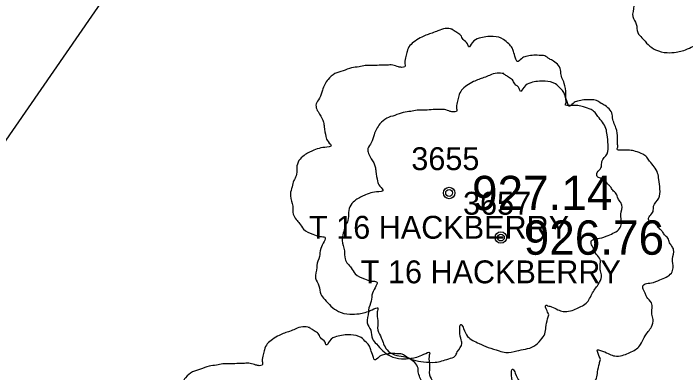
# Model space of a CAD drawing. Extents: x 1575382 to 1578175, y 1099175 to 1101955.
# Drawn here: x 1577367.12 to 1577396.51, y 1100879.44 to 1100895.14 of the extents above; entities that cross this region are included whole.
import ezdxf

# ---------------------------------------------------------------- set-up
doc = ezdxf.new("R2010")
doc.units = 0
for name, color, linetype in [('RD_EX_Conc', 7, 'Continuous'), ('RD_EX_TX_VEG_ELEV', 7, 'Continuous'), ('RD_EX_VEG', 7, 'Continuous'), ('RD_EX_VEG_txCode', 7, 'Continuous'), ('RD_SMD_Locator', 7, 'Continuous')]:
    doc.layers.add(name, color=color, linetype=linetype)

msp = doc.modelspace()

# ---------------------------------------------------------------- linework, layer by layer
at = {"layer": 'RD_EX_Conc'}
msp.add_lwpolyline([(1577353.203, 1100869.936), (1577378.592, 1100906.687), (1577381.828, 1100910.062), (1577386.394, 1100913.088)], dxfattribs=at)
at = {"layer": 'RD_EX_VEG'}
for centre, radius in [((1577386.17, 1100887.293), 0.25), ((1577386.157, 1100887.274), 0.0001), ((1577388.432, 1100885.344), 0.25), ((1577388.419, 1100885.325), 0.0001)]:
    msp.add_circle(centre, radius, dxfattribs=at)
for points in [[(1577400.17, 1100905.899), (1577399.87, 1100905.924), (1577399.545, 1100905.824), (1577399.295, 1100905.724), (1577399.07, 1100905.649), (1577398.845, 1100905.549), (1577398.545, 1100905.374), (1577398.321, 1100905.174), (1577398.196, 1100904.924), (1577398.146, 1100904.699), (1577398.096, 1100904.424), (1577398.096, 1100904.249), (1577397.971, 1100904.224), (1577397.821, 1100904.249), (1577397.571, 1100904.324), (1577397.321, 1100904.324), (1577397.071, 1100904.324), (1577396.721, 1100904.299), (1577396.371, 1100904.299), (1577396.097, 1100904.249), (1577395.772, 1100904.199), (1577395.397, 1100904.074), (1577395.047, 1100903.949), (1577394.747, 1100903.7), (1577394.497, 1100903.225), (1577394.372, 1100902.875), (1577394.222, 1100902.625), (1577394.372, 1100902.175), (1577394.547, 1100901.825), (1577394.572, 1100901.625), (1577394.647, 1100901.201), (1577394.747, 1100900.976), (1577394.872, 1100900.776), (1577394.797, 1100900.751), (1577394.422, 1100900.701), (1577394.122, 1100900.601), (1577393.698, 1100900.376), (1577393.473, 1100900.151), (1577393.373, 1100899.826), (1577393.348, 1100899.476), (1577393.248, 1100899.277), (1577393.173, 1100899.002), (1577393.148, 1100898.927), (1577393.098, 1100898.602), (1577393.198, 1100898.152), (1577393.223, 1100897.802), (1577393.348, 1100897.577), (1577393.498, 1100897.402), (1577393.673, 1100897.152), (1577394.072, 1100896.928), (1577394.397, 1100896.828), (1577394.597, 1100896.803), (1577394.422, 1100896.303), (1577394.372, 1100895.953), (1577394.247, 1100895.553), (1577394.247, 1100895.478), (1577394.197, 1100895.003), (1577394.347, 1100894.678), (1577394.422, 1100894.304), (1577394.597, 1100894.079), (1577394.872, 1100893.779), (1577395.197, 1100893.554), (1577395.697, 1100893.429), (1577396.097, 1100893.454), (1577396.671, 1100893.629), (1577396.921, 1100893.704), (1577396.896, 1100893.529), (1577396.921, 1100893.154), (1577396.921, 1100892.729), (1577397.071, 1100892.405), (1577397.171, 1100892.13), (1577397.321, 1100891.88), (1577397.646, 1100891.655), (1577398.046, 1100891.58), (1577398.47, 1100891.43), (1577398.92, 1100891.355), (1577399.42, 1100891.33), (1577400.02, 1100891.48), (1577400.295, 1100891.605), (1577400.395, 1100891.78), (1577400.595, 1100892.155), (1577400.545, 1100892.38), (1577400.57, 1100892.979), (1577400.669, 1100892.804), (1577400.844, 1100892.454), (1577401.344, 1100892.155), (1577401.744, 1100891.98), (1577402.219, 1100891.83), (1577402.519, 1100891.755), (1577402.993, 1100891.83), (1577403.368, 1100891.905), (1577403.743, 1100892.03), (1577404.043, 1100892.305), (1577404.218, 1100892.579), (1577404.268, 1100892.854), (1577404.343, 1100893.229), (1577404.393, 1100893.404)], [(1577386.302, 1100894.46), (1577386.002, 1100894.485), (1577385.677, 1100894.385), (1577385.427, 1100894.285), (1577385.202, 1100894.21), (1577384.978, 1100894.11), (1577384.678, 1100893.935), (1577384.453, 1100893.735), (1577384.328, 1100893.486), (1577384.278, 1100893.261), (1577384.228, 1100892.986), (1577384.228, 1100892.811), (1577384.103, 1100892.786), (1577383.953, 1100892.811), (1577383.703, 1100892.886), (1577383.453, 1100892.886), (1577383.203, 1100892.886), (1577382.853, 1100892.861), (1577382.504, 1100892.861), (1577382.229, 1100892.811), (1577381.904, 1100892.761), (1577381.529, 1100892.636), (1577381.179, 1100892.511), (1577380.879, 1100892.261), (1577380.629, 1100891.786), (1577380.504, 1100891.436), (1577380.355, 1100891.187), (1577380.504, 1100890.737), (1577380.679, 1100890.387), (1577380.704, 1100890.187), (1577380.779, 1100889.762), (1577380.879, 1100889.537), (1577381.004, 1100889.337), (1577380.929, 1100889.312), (1577380.554, 1100889.262), (1577380.255, 1100889.162), (1577379.83, 1100888.938), (1577379.605, 1100888.713), (1577379.505, 1100888.388), (1577379.48, 1100888.038), (1577379.38, 1100887.838), (1577379.305, 1100887.563), (1577379.28, 1100887.488), (1577379.23, 1100887.163), (1577379.33, 1100886.713), (1577379.355, 1100886.364), (1577379.48, 1100886.139), (1577379.63, 1100885.964), (1577379.805, 1100885.714), (1577380.205, 1100885.489), (1577380.529, 1100885.389), (1577380.729, 1100885.364), (1577380.554, 1100884.864), (1577380.504, 1100884.514), (1577380.38, 1100884.115), (1577380.38, 1100884.04), (1577380.33, 1100883.565), (1577380.479, 1100883.24), (1577380.554, 1100882.865), (1577380.729, 1100882.64), (1577381.004, 1100882.34), (1577381.329, 1100882.116), (1577381.829, 1100881.991), (1577382.229, 1100882.016), (1577382.804, 1100882.19), (1577383.053, 1100882.265), (1577383.028, 1100882.091), (1577383.053, 1100881.716), (1577383.053, 1100881.291), (1577383.203, 1100880.966), (1577383.303, 1100880.691), (1577383.453, 1100880.441), (1577383.778, 1100880.216), (1577384.178, 1100880.141), (1577384.603, 1100879.991), (1577385.053, 1100879.916), (1577385.552, 1100879.891), (1577386.152, 1100880.041), (1577386.427, 1100880.166), (1577386.527, 1100880.341), (1577386.727, 1100880.716), (1577386.677, 1100880.941), (1577386.702, 1100881.541), (1577386.802, 1100881.366), (1577386.977, 1100881.016), (1577387.476, 1100880.716), (1577387.876, 1100880.541), (1577388.351, 1100880.391), (1577388.651, 1100880.316), (1577389.126, 1100880.391), (1577389.501, 1100880.466), (1577389.875, 1100880.591), (1577390.175, 1100880.866), (1577390.35, 1100881.141), (1577390.4, 1100881.416), (1577390.475, 1100881.791), (1577390.525, 1100881.966)], [(1577390.525, 1100881.966), (1577390.45, 1100882.141), (1577390.4, 1100882.39), (1577390.475, 1100882.365), (1577390.65, 1100882.315), (1577390.925, 1100882.19), (1577391.15, 1100882.116), (1577391.475, 1100882.141), (1577391.75, 1100882.24), (1577392.199, 1100882.515), (1577392.474, 1100882.99), (1577392.749, 1100883.39), (1577392.824, 1100883.715), (1577392.774, 1100883.94), (1577392.749, 1100884.439), (1577392.549, 1100884.689), (1577392.499, 1100884.814), (1577392.399, 1100885.214), (1577392.474, 1100885.264), (1577392.749, 1100885.314), (1577393.124, 1100885.439), (1577393.399, 1100885.564), (1577393.624, 1100885.739), (1577393.699, 1100885.964), (1577393.674, 1100886.364), (1577393.724, 1100886.763), (1577393.649, 1100886.913), (1577393.549, 1100887.063), (1577393.474, 1100887.263), (1577393.324, 1100887.413), (1577393.224, 1100887.563), (1577393.124, 1100887.663), (1577392.999, 1100887.813), (1577392.824, 1100887.938), (1577392.674, 1100887.988), (1577392.624, 1100888.138), (1577392.774, 1100888.338), (1577392.824, 1100888.438), (1577392.849, 1100888.663), (1577393.074, 1100889.012), (1577393.124, 1100889.412), (1577393.074, 1100889.837), (1577393.024, 1100890.112), (1577392.874, 1100890.387), (1577392.674, 1100890.637), (1577392.549, 1100890.812), (1577392.374, 1100890.937), (1577392.049, 1100891.062), (1577391.8, 1100891.112), (1577391.45, 1100891.112), (1577391.25, 1100891.162), (1577391.275, 1100891.212), (1577391.275, 1100891.361), (1577391.275, 1100891.636), (1577391.2, 1100892.086), (1577391.05, 1100892.586), (1577391.05, 1100892.611), (1577390.95, 1100892.861), (1577390.725, 1100893.061), (1577390.55, 1100893.161), (1577390.35, 1100893.286), (1577390.1, 1100893.311), (1577389.8, 1100893.311), (1577389.526, 1100893.261), (1577389.326, 1100893.161), (1577389.151, 1100893.036), (1577389.076, 1100893.186), (1577388.976, 1100893.486), (1577388.926, 1100893.635), (1577388.776, 1100893.81), (1577388.551, 1100894.01), (1577388.101, 1100894.135), (1577387.476, 1100894.06), (1577387.177, 1100893.86), (1577387.027, 1100893.685), (1577386.977, 1100893.81), (1577386.777, 1100894.01), (1577386.677, 1100894.185), (1577386.502, 1100894.31), (1577386.352, 1100894.41), (1577386.252, 1100894.46)], [(1577388.564, 1100892.511), (1577388.264, 1100892.536), (1577387.939, 1100892.436), (1577387.689, 1100892.336), (1577387.464, 1100892.261), (1577387.239, 1100892.161), (1577386.939, 1100891.987), (1577386.714, 1100891.787), (1577386.589, 1100891.537), (1577386.539, 1100891.312), (1577386.49, 1100891.037), (1577386.49, 1100890.862), (1577386.365, 1100890.837), (1577386.215, 1100890.862), (1577385.965, 1100890.937), (1577385.715, 1100890.937), (1577385.465, 1100890.937), (1577385.115, 1100890.912), (1577384.765, 1100890.912), (1577384.49, 1100890.862), (1577384.166, 1100890.812), (1577383.791, 1100890.687), (1577383.441, 1100890.562), (1577383.141, 1100890.312), (1577382.891, 1100889.838), (1577382.766, 1100889.488), (1577382.616, 1100889.238), (1577382.766, 1100888.788), (1577382.941, 1100888.438), (1577382.966, 1100888.238), (1577383.041, 1100887.813), (1577383.141, 1100887.589), (1577383.266, 1100887.389), (1577383.191, 1100887.364), (1577382.816, 1100887.314), (1577382.516, 1100887.214), (1577382.091, 1100886.989), (1577381.867, 1100886.764), (1577381.767, 1100886.439), (1577381.742, 1100886.089), (1577381.642, 1100885.889), (1577381.567, 1100885.614), (1577381.542, 1100885.539), (1577381.492, 1100885.215), (1577381.592, 1100884.765), (1577381.617, 1100884.415), (1577381.742, 1100884.19), (1577381.892, 1100884.015), (1577382.066, 1100883.765), (1577382.466, 1100883.54), (1577382.791, 1100883.44), (1577382.991, 1100883.415), (1577382.816, 1100882.916), (1577382.766, 1100882.566), (1577382.641, 1100882.166), (1577382.641, 1100882.091), (1577382.591, 1100881.616), (1577382.741, 1100881.291), (1577382.816, 1100880.916), (1577382.991, 1100880.692), (1577383.266, 1100880.392), (1577383.591, 1100880.167), (1577384.091, 1100880.042), (1577384.49, 1100880.067), (1577385.065, 1100880.242), (1577385.315, 1100880.317), (1577385.29, 1100880.142), (1577385.315, 1100879.767), (1577385.315, 1100879.342), (1577385.465, 1100879.017), (1577385.565, 1100878.742), (1577385.715, 1100878.492), (1577386.04, 1100878.268), (1577386.44, 1100878.193), (1577386.864, 1100878.043), (1577387.314, 1100877.968), (1577387.814, 1100877.943), (1577388.414, 1100878.093), (1577388.689, 1100878.218), (1577388.789, 1100878.393), (1577388.988, 1100878.767), (1577388.938, 1100878.992), (1577388.963, 1100879.592), (1577389.063, 1100879.417), (1577389.238, 1100879.067), (1577389.738, 1100878.767), (1577390.138, 1100878.592), (1577390.613, 1100878.442), (1577390.913, 1100878.368), (1577391.387, 1100878.442), (1577391.762, 1100878.517), (1577392.137, 1100878.642), (1577392.437, 1100878.917), (1577392.612, 1100879.192), (1577392.662, 1100879.467), (1577392.737, 1100879.842), (1577392.787, 1100880.017)], [(1577392.787, 1100880.017), (1577392.712, 1100880.192), (1577392.662, 1100880.442), (1577392.737, 1100880.417), (1577392.912, 1100880.367), (1577393.187, 1100880.242), (1577393.412, 1100880.167), (1577393.736, 1100880.192), (1577394.011, 1100880.292), (1577394.461, 1100880.567), (1577394.736, 1100881.041), (1577395.011, 1100881.441), (1577395.086, 1100881.766), (1577395.036, 1100881.991), (1577395.011, 1100882.491), (1577394.811, 1100882.741), (1577394.761, 1100882.866), (1577394.661, 1100883.265), (1577394.736, 1100883.315), (1577395.011, 1100883.365), (1577395.386, 1100883.49), (1577395.661, 1100883.615), (1577395.885, 1100883.79), (1577395.96, 1100884.015), (1577395.935, 1100884.415), (1577395.985, 1100884.815), (1577395.91, 1100884.965), (1577395.81, 1100885.115), (1577395.735, 1100885.315), (1577395.586, 1100885.464), (1577395.486, 1100885.614), (1577395.386, 1100885.714), (1577395.261, 1100885.864), (1577395.086, 1100885.989), (1577394.936, 1100886.039), (1577394.886, 1100886.189), (1577395.036, 1100886.389), (1577395.086, 1100886.489), (1577395.111, 1100886.714), (1577395.336, 1100887.064), (1577395.386, 1100887.464), (1577395.336, 1100887.888), (1577395.286, 1100888.163), (1577395.136, 1100888.438), (1577394.936, 1100888.688), (1577394.811, 1100888.863), (1577394.636, 1100888.988), (1577394.311, 1100889.113), (1577394.061, 1100889.163), (1577393.711, 1100889.163), (1577393.511, 1100889.213), (1577393.536, 1100889.263), (1577393.536, 1100889.413), (1577393.536, 1100889.688), (1577393.461, 1100890.137), (1577393.312, 1100890.637), (1577393.312, 1100890.662), (1577393.212, 1100890.912), (1577392.987, 1100891.112), (1577392.812, 1100891.212), (1577392.612, 1100891.337), (1577392.362, 1100891.362), (1577392.062, 1100891.362), (1577391.787, 1100891.312), (1577391.587, 1100891.212), (1577391.412, 1100891.087), (1577391.337, 1100891.237), (1577391.237, 1100891.537), (1577391.187, 1100891.687), (1577391.038, 1100891.862), (1577390.813, 1100892.062), (1577390.363, 1100892.186), (1577389.738, 1100892.112), (1577389.438, 1100891.912), (1577389.288, 1100891.737), (1577389.238, 1100891.862), (1577389.038, 1100892.062), (1577388.938, 1100892.236), (1577388.764, 1100892.361), (1577388.614, 1100892.461), (1577388.514, 1100892.511)], [(1577380.069, 1100881.417), (1577379.769, 1100881.442), (1577379.444, 1100881.342), (1577379.195, 1100881.242), (1577378.97, 1100881.167), (1577378.745, 1100881.067), (1577378.445, 1100880.892), (1577378.22, 1100880.692), (1577378.095, 1100880.442), (1577378.045, 1100880.217), (1577377.995, 1100879.942), (1577377.995, 1100879.767), (1577377.87, 1100879.742), (1577377.72, 1100879.767), (1577377.47, 1100879.842), (1577377.22, 1100879.842), (1577376.97, 1100879.842), (1577376.621, 1100879.817), (1577376.271, 1100879.817), (1577375.996, 1100879.767), (1577375.671, 1100879.717), (1577375.296, 1100879.592), (1577374.946, 1100879.467), (1577374.647, 1100879.217), (1577374.397, 1100878.743), (1577374.272, 1100878.393), (1577374.122, 1100878.143), (1577374.272, 1100877.693), (1577374.447, 1100877.343), (1577374.472, 1100877.143), (1577374.547, 1100876.719), (1577374.647, 1100876.494), (1577374.771, 1100876.294), (1577374.697, 1100876.269), (1577374.322, 1100876.219), (1577374.022, 1100876.119), (1577373.597, 1100875.894), (1577373.372, 1100875.669), (1577373.272, 1100875.344), (1577373.247, 1100874.994), (1577373.147, 1100874.794), (1577373.072, 1100874.52), (1577373.047, 1100874.445), (1577372.997, 1100874.12), (1577373.097, 1100873.67), (1577373.122, 1100873.32), (1577373.247, 1100873.095), (1577373.397, 1100872.92), (1577373.572, 1100872.67), (1577373.972, 1100872.445), (1577374.297, 1100872.345), (1577374.497, 1100872.321), (1577374.322, 1100871.821), (1577374.272, 1100871.471), (1577374.147, 1100871.071), (1577374.147, 1100870.996), (1577374.097, 1100870.521), (1577374.247, 1100870.196), (1577374.322, 1100869.822), (1577374.497, 1100869.597), (1577374.771, 1100869.297), (1577375.096, 1100869.072), (1577375.596, 1100868.947), (1577375.996, 1100868.972), (1577376.571, 1100869.147), (1577376.821, 1100869.222), (1577376.796, 1100869.047), (1577376.821, 1100868.672), (1577376.821, 1100868.247), (1577376.97, 1100867.922), (1577377.07, 1100867.648), (1577377.22, 1100867.398), (1577377.545, 1100867.173), (1577377.945, 1100867.098), (1577378.37, 1100866.948), (1577378.82, 1100866.873), (1577379.319, 1100866.848), (1577379.919, 1100866.998), (1577380.194, 1100867.123), (1577380.294, 1100867.298), (1577380.494, 1100867.673), (1577380.444, 1100867.897), (1577380.469, 1100868.497), (1577380.569, 1100868.322), (1577380.744, 1100867.972), (1577381.244, 1100867.673), (1577381.643, 1100867.498), (1577382.118, 1100867.348), (1577382.418, 1100867.273), (1577382.893, 1100867.348), (1577383.268, 1100867.423), (1577383.643, 1100867.548), (1577383.942, 1100867.822), (1577384.117, 1100868.097), (1577384.167, 1100868.372), (1577384.242, 1100868.747), (1577384.292, 1100868.922)], [(1577384.292, 1100868.922), (1577384.217, 1100869.097), (1577384.167, 1100869.347), (1577384.242, 1100869.322), (1577384.417, 1100869.272), (1577384.692, 1100869.147), (1577384.917, 1100869.072), (1577385.242, 1100869.097), (1577385.517, 1100869.197), (1577385.967, 1100869.472), (1577386.241, 1100869.947), (1577386.516, 1100870.346), (1577386.591, 1100870.671), (1577386.541, 1100870.896), (1577386.516, 1100871.396), (1577386.316, 1100871.646), (1577386.266, 1100871.771), (1577386.166, 1100872.171), (1577386.241, 1100872.221), (1577386.516, 1100872.271), (1577386.891, 1100872.395), (1577387.166, 1100872.52), (1577387.391, 1100872.695), (1577387.466, 1100872.92), (1577387.441, 1100873.32), (1577387.491, 1100873.72), (1577387.416, 1100873.87), (1577387.316, 1100874.02), (1577387.241, 1100874.22), (1577387.091, 1100874.37), (1577386.991, 1100874.52), (1577386.891, 1100874.619), (1577386.766, 1100874.769), (1577386.591, 1100874.894), (1577386.441, 1100874.944), (1577386.391, 1100875.094), (1577386.541, 1100875.294), (1577386.591, 1100875.394), (1577386.616, 1100875.619), (1577386.841, 1100875.969), (1577386.891, 1100876.369), (1577386.841, 1100876.794), (1577386.791, 1100877.068), (1577386.641, 1100877.343), (1577386.441, 1100877.593), (1577386.316, 1100877.768), (1577386.141, 1100877.893), (1577385.817, 1100878.018), (1577385.567, 1100878.068), (1577385.217, 1100878.068), (1577385.017, 1100878.118), (1577385.042, 1100878.168), (1577385.042, 1100878.318), (1577385.042, 1100878.593), (1577384.967, 1100879.043), (1577384.817, 1100879.542), (1577384.817, 1100879.567), (1577384.717, 1100879.817), (1577384.492, 1100880.017), (1577384.317, 1100880.117), (1577384.117, 1100880.242), (1577383.867, 1100880.267), (1577383.568, 1100880.267), (1577383.293, 1100880.217), (1577383.093, 1100880.117), (1577382.918, 1100879.992), (1577382.843, 1100880.142), (1577382.743, 1100880.442), (1577382.693, 1100880.592), (1577382.543, 1100880.767), (1577382.318, 1100880.967), (1577381.868, 1100881.092), (1577381.244, 1100881.017), (1577380.944, 1100880.817), (1577380.794, 1100880.642), (1577380.744, 1100880.767), (1577380.544, 1100880.967), (1577380.444, 1100881.142), (1577380.269, 1100881.267), (1577380.119, 1100881.367), (1577380.019, 1100881.417)]]:
    msp.add_spline(points, degree=3, dxfattribs=at)
at = {"layer": 'RD_SMD_Locator'}
for centre in [(1577386.17, 1100887.293), (1577388.432, 1100885.344)]:
    msp.add_circle(centre, 0.15, dxfattribs=at)

# ---------------------------------------------------------------- texts
at = {"layer": 'RD_EX_TX_VEG_ELEV'}
for s, p in [('927.14', (1577387.17, 1100886.543)), ('926.76', (1577389.432, 1100884.594))]:
    msp.add_text(s, height=1.5, dxfattribs=at).set_placement(p)
at = {"layer": 'RD_EX_VEG_txCode'}
for s, p in [('3655', (1577384.516, 1100888.293)), ('3657', (1577386.778, 1100886.344)), ('T 16 HACKBERRY', (1577380.044, 1100885.293)), ('T 16 HACKBERRY', (1577382.306, 1100883.344))]:
    msp.add_text(s, height=1, dxfattribs=at).set_placement(p)

doc.saveas('drawing.dxf')
